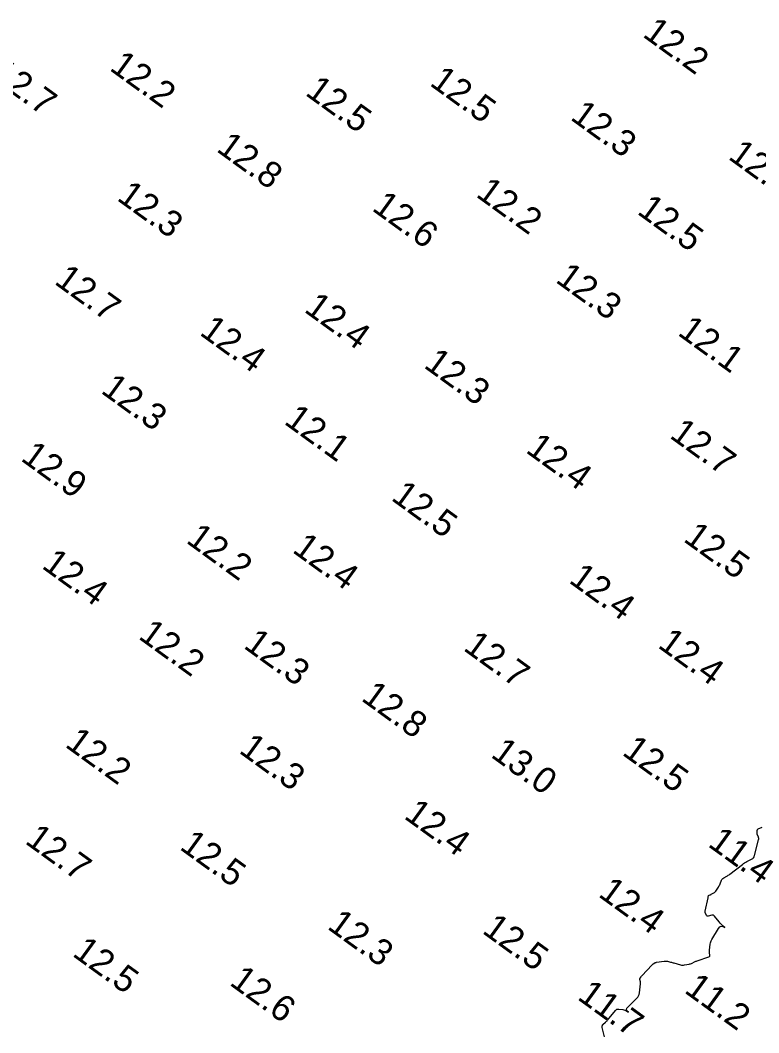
# Model space of a CAD drawing. Extents: x 815352 to 820877, y 582403 to 597439.
# Drawn here: x 818829.3 to 818971.4, y 587213.7 to 587408.6 of the extents above; entities that cross this region are included whole.
import ezdxf

# ---------------------------------------------------------------- set-up
doc = ezdxf.new("R2010")
doc.units = 0
doc.layers.add('V-CONT-EL12', color=7, linetype='Continuous')
doc.layers.add('V-TOPO-SOUN', color=7, linetype='Continuous')

msp = doc.modelspace()

# ---------------------------------------------------------------- linework, layer by layer
at = {"layer": 'V-CONT-EL12'}
msp.add_lwpolyline([(818941.76, 587212.89), (818941.31, 587214.69), (818941.3, 587214.74), (818941.3, 587214.79), (818941.3, 587214.84), (818941.3, 587214.89), (818941.34, 587215.1), (818941.35, 587215.15), (818941.38, 587215.19), (818941.4, 587215.23), (818941.44, 587215.27), (818941.95, 587215.7), (818942.05, 587215.79), (818942.14, 587215.88), (818942.23, 587215.97), (818942.31, 587216.07), (818943.84, 587217.95), (818943.97, 587218.09), (818944.13, 587218.18), (818944.3, 587218.22), (818944.49, 587218.22), (818945.3, 587218.12), (818945.49, 587218.08), (818945.68, 587218.02), (818945.86, 587217.94), (818946.03, 587217.84), (818946.37, 587217.6), (818946.11, 587217.84), (818946.01, 587218.1), (818946.07, 587218.36), (818946.28, 587218.64), (818947.95, 587220.28), (818948.15, 587220.51), (818948.31, 587220.77), (818948.42, 587221.05), (818948.48, 587221.36), (818948.69, 587223.04), (818948.7, 587223.15), (818948.7, 587223.25), (818948.69, 587223.35), (818948.67, 587223.45), (818948.55, 587223.9), (818948.54, 587223.98), (818948.54, 587224.05), (818948.57, 587224.12), (818948.61, 587224.19), (818948.79, 587224.45), (818948.84, 587224.52), (818948.89, 587224.58), (818948.94, 587224.64), (818949, 587224.7), (818950.84, 587226.67), (818950.9, 587226.73), (818950.97, 587226.79), (818951.04, 587226.85), (818951.11, 587226.9), (818951.42, 587227.1), (818951.5, 587227.15), (818951.58, 587227.19), (818951.66, 587227.21), (818951.75, 587227.23), (818953.25, 587227.44), (818953.41, 587227.46), (818953.56, 587227.46), (818953.72, 587227.44), (818953.87, 587227.41), (818954.48, 587227.26), (818954.63, 587227.22), (818954.78, 587227.18), (818954.94, 587227.14), (818955.09, 587227.1), (818956.39, 587226.73), (818956.58, 587226.69), (818956.77, 587226.67), (818956.97, 587226.68), (818957.16, 587226.7), (818958.07, 587226.88), (818958.2, 587226.91), (818958.33, 587226.95), (818958.46, 587227), (818958.59, 587227.06), (818959.08, 587227.3), (818959.2, 587227.36), (818959.33, 587227.41), (818959.45, 587227.46), (818959.58, 587227.51), (818961.85, 587228.27), (818961.95, 587228.32), (818962.02, 587228.38), (818962.05, 587228.47), (818962.04, 587228.58), (818961.97, 587229.06), (818961.95, 587229.18), (818961.95, 587229.3), (818961.95, 587229.42), (818961.96, 587229.54), (818962.09, 587230.71), (818962.12, 587230.94), (818962.18, 587231.17), (818962.27, 587231.38), (818962.38, 587231.59), (818963.66, 587233.7), (818963.93, 587234.03), (818964.23, 587234.17), (818964.55, 587234.12), (818964.9, 587233.89), (818964.61, 587234.15), (818964.39, 587234.35), (818964.19, 587234.56), (818963.99, 587234.77), (818963.81, 587235), (818962.92, 587236.11), (818962.82, 587236.22), (818962.7, 587236.28), (818962.56, 587236.3), (818962.41, 587236.29), (818961.69, 587236.11), (818961.59, 587236.1), (818961.51, 587236.12), (818961.43, 587236.17), (818961.38, 587236.26), (818961.17, 587236.66), (818961.13, 587236.76), (818961.11, 587236.86), (818961.11, 587236.97), (818961.12, 587237.08), (818961.72, 587239.61), (818961.72, 587239.63), (818961.72, 587239.65), (818961.72, 587239.66), (818961.72, 587239.68), (818961.7, 587239.76), (818961.7, 587239.78), (818961.7, 587239.8), (818961.7, 587239.81), (818961.7, 587239.83), (818961.78, 587240.05), (818961.8, 587240.09), (818961.83, 587240.12), (818961.86, 587240.14), (818961.9, 587240.16), (818962.11, 587240.23), (818962.15, 587240.24), (818962.2, 587240.26), (818962.25, 587240.28), (818962.29, 587240.31), (818962.82, 587240.61), (818962.92, 587240.67), (818963.01, 587240.74), (818963.09, 587240.83), (818963.16, 587240.92), (818963.66, 587241.67), (818963.76, 587241.82), (818963.84, 587241.98), (818963.92, 587242.14), (818963.99, 587242.3), (818964.27, 587243), (818964.34, 587243.14), (818964.44, 587243.27), (818964.55, 587243.38), (818964.69, 587243.47), (818965.28, 587243.8), (818965.43, 587243.88), (818965.57, 587243.97), (818965.71, 587244.07), (818965.85, 587244.17), (818968.3, 587246.07), (818968.5, 587246.22), (818968.71, 587246.36), (818968.93, 587246.49), (818969.15, 587246.6), (818970.06, 587247.05), (818970.27, 587247.18), (818970.43, 587247.34), (818970.56, 587247.54), (818970.64, 587247.77), (818971.4, 587250.83), (818971.42, 587250.96), (818971.42, 587251.09), (818971.4, 587251.21), (818971.37, 587251.34), (818971.15, 587251.9), (818971.13, 587251.99), (818971.11, 587252.08), (818971.1, 587252.17), (818971.11, 587252.26), (818971.15, 587252.63), (818971.17, 587252.72), (818971.21, 587252.79), (818971.26, 587252.84), (818971.34, 587252.89), (818972.07, 587253.21)], dxfattribs=at)

# ---------------------------------------------------------------- texts
at = {"layer": 'V-TOPO-SOUN'}
for s, p in [('12.2 ', (818948.89, 587405.58)), ('12.2 ', (818846.3, 587399.12)), ('12.7 ', (818823.37, 587397.58)), ('12.5 ', (818907.91, 587396.2)), ('12.5 ', (818883.96, 587394.33)), ('12.3 ', (818934.98, 587389.61)), ('12.8 ', (818866.87, 587383.5)), ('12.7 ', (818965.36, 587382.03)), ('12.3 ', (818847.71, 587374.09)), ('12.2 ', (818916.81, 587374.78)), ('12.6 ', (818896.8, 587372.11)), ('12.5 ', (818947.83, 587371.46)), ('12.7 ', (818835.67, 587357.98)), ('12.3 ', (818932.13, 587358.31)), ('12.4 ', (818883.74, 587352.6)), ('12.4 ', (818863.63, 587348.17)), ('12.1 ', (818955.64, 587348.13)), ('12.3 ', (818906.77, 587341.87)), ('12.3 ', (818844.63, 587336.98)), ('12.1 ', (818879.88, 587331.03)), ('12.7 ', (818954.08, 587328.35)), ('12.4 ', (818926.39, 587325.53)), ('12.9 ', (818829.21, 587323.96)), ('12.5 ', (818900.49, 587316.35)), ('12.2 ', (818861.03, 587308.14)), ('12.5 ', (818956.73, 587308.41)), ('12.4 ', (818881.47, 587306.31)), ('12.4 ', (818833.25, 587303.25)), ('12.4 ', (818934.69, 587300.47)), ('12.2 ', (818851.85, 587289.67)), ('12.3 ', (818872.09, 587287.87)), ('12.4 ', (818951.81, 587287.97)), ('12.7 ', (818914.38, 587287.44)), ('12.8 ', (818894.73, 587277.76)), ('12.2 ', (818837.74, 587268.84)), ('12.3 ', (818871.2, 587267.69)), ('13.0 ', (818919.67, 587266.88)), ('12.5 ', (818944.95, 587267.3)), ('12.4 ', (818902.96, 587255.06)), ('12.7 ', (818830.03, 587250.24)), ('12.5 ', (818859.78, 587249.12)), ('11.4 ', (818961.46, 587249.68)), ('12.4 ', (818940.36, 587240.03)), ('12.3 ', (818888.2, 587233.8)), ('12.5 ', (818918.01, 587232.98)), ('12.5 ', (818839.14, 587228.58)), ('12.6 ', (818869.38, 587223)), ('11.2 ', (818956.9, 587221.53)), ('11.7 ', (818936.33, 587220.22))]:
    msp.add_text(s, height=5, rotation=324, dxfattribs=at).set_placement(p)

doc.saveas('drawing.dxf')
